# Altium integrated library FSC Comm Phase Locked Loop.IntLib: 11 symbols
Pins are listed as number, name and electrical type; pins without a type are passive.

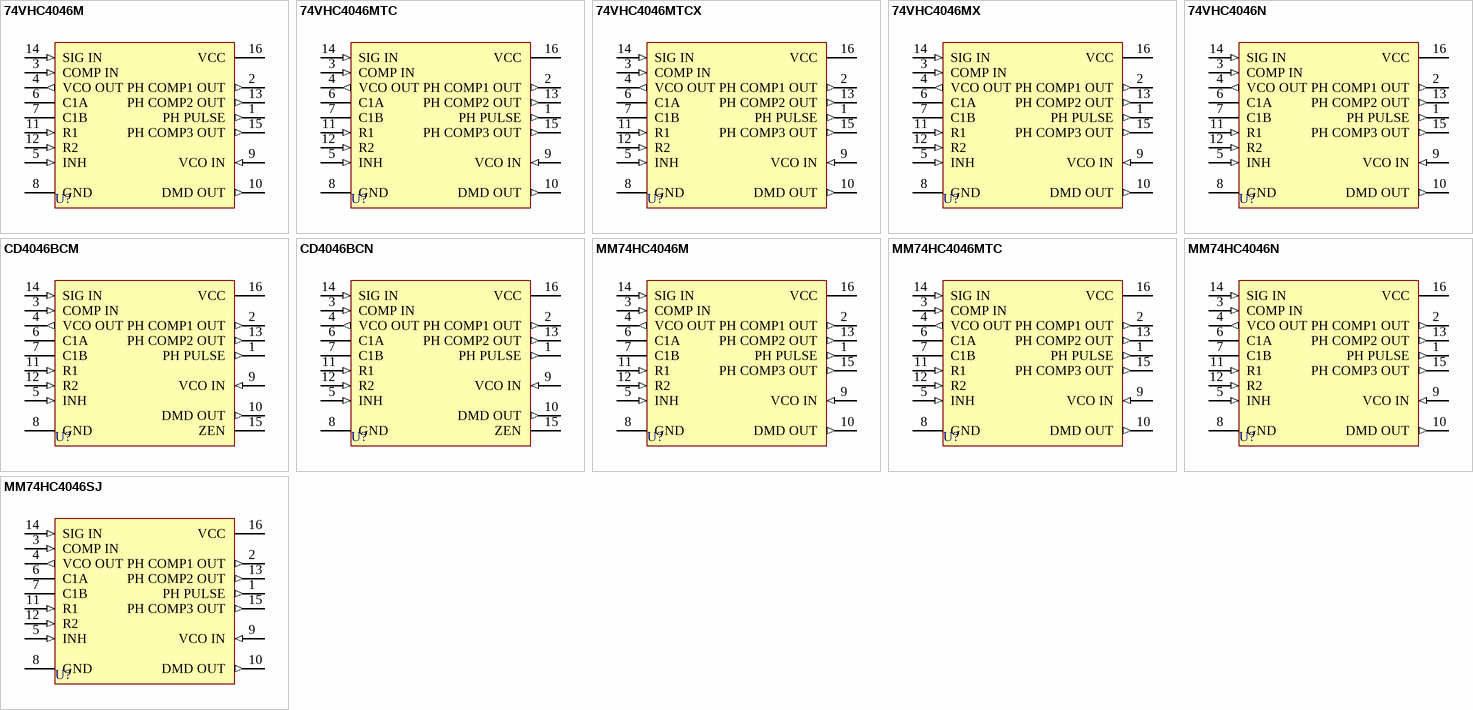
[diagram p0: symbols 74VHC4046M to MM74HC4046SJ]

## 74VHC4046M
designator U?
CMOS Phase Lock Loop
footprint M16A_N (SOIC, 16-Leads, Body 9.9x3.9mm, Pitch 1.27mm, IPC Medium Density)
footprint M16A_L (SOIC, 16-Leads, Body 9.9x3.9mm, Pitch 1.27mm, IPC High Density)
footprint M16A_M (SOIC, 16-Leads, Body 9.9x3.9mm, Pitch 1.27mm, IPC Low Density)
3D model M16A (16-Pin Small Outline Integrated Circuit 1.27 mm Pitch)
pins: 1 PH PULSE (out), 2 PH COMP1 OUT (out), 3 COMP IN (in), 4 VCO OUT (out), 5 INH (in), 6 C1A, 7 C1B, 8 GND (power), 9 VCO IN (in), 10 DMD OUT (out), 11 R1 (in), 12 R2 (in), 13 PH COMP2 OUT (out), 14 SIG IN (in), 15 PH COMP3 OUT (out), 16 VCC (power)

## 74VHC4046MTC
designator U?
CMOS Phase Lock Loop
footprint MTC16 (Shrink Small Outline; 16 Leads; Body Width 4.4 mm; Pitch 0.65 mm)
3D model MTC16 (Shrink Small Outline; 16 Leads; Body Width 4.4 mm; Pitch 0.65 mm)
pins: 1 PH PULSE (out), 2 PH COMP1 OUT (out), 3 COMP IN (in), 4 VCO OUT (out), 5 INH (in), 6 C1A, 7 C1B, 8 GND (power), 9 VCO IN (in), 10 DMD OUT (out), 11 R1 (in), 12 R2 (in), 13 PH COMP2 OUT (out), 14 SIG IN (in), 15 PH COMP3 OUT (out), 16 VCC (power)

## 74VHC4046MTCX
designator U?
CMOS Phase Lock Loop
footprint MTC16 (Shrink Small Outline; 16 Leads; Body Width 4.4 mm; Pitch 0.65 mm)
3D model MTC16 (Shrink Small Outline; 16 Leads; Body Width 4.4 mm; Pitch 0.65 mm)
pins: 1 PH PULSE (out), 2 PH COMP1 OUT (out), 3 COMP IN (in), 4 VCO OUT (out), 5 INH (in), 6 C1A, 7 C1B, 8 GND (power), 9 VCO IN (in), 10 DMD OUT (out), 11 R1 (in), 12 R2 (in), 13 PH COMP2 OUT (out), 14 SIG IN (in), 15 PH COMP3 OUT (out), 16 VCC (power)

## 74VHC4046MX
designator U?
CMOS Phase Lock Loop
footprint M16A_N (SOIC, 16-Leads, Body 9.9x3.9mm, Pitch 1.27mm, IPC Medium Density)
footprint M16A_L (SOIC, 16-Leads, Body 9.9x3.9mm, Pitch 1.27mm, IPC High Density)
footprint M16A_M (SOIC, 16-Leads, Body 9.9x3.9mm, Pitch 1.27mm, IPC Low Density)
3D model M16A (16-Pin Small Outline Integrated Circuit 1.27 mm Pitch)
pins: 1 PH PULSE (out), 2 PH COMP1 OUT (out), 3 COMP IN (in), 4 VCO OUT (out), 5 INH (in), 6 C1A, 7 C1B, 8 GND (power), 9 VCO IN (in), 10 DMD OUT (out), 11 R1 (in), 12 R2 (in), 13 PH COMP2 OUT (out), 14 SIG IN (in), 15 PH COMP3 OUT (out), 16 VCC (power)

## 74VHC4046N
designator U?
CMOS Phase Lock Loop
footprint N16E (DIP; 16 Leads; Row Spacing 7.62 mm; Pitch 2.54 mm)
3D model N16E (DIP; 16 Leads; Row Spacing 7.62 mm; Pitch 2.54 mm)
pins: 1 PH PULSE (out), 2 PH COMP1 OUT (out), 3 COMP IN (in), 4 VCO OUT (out), 5 INH (in), 6 C1A, 7 C1B, 8 GND (power), 9 VCO IN (in), 10 DMD OUT (out), 11 R1 (in), 12 R2 (in), 13 PH COMP2 OUT (out), 14 SIG IN (in), 15 PH COMP3 OUT (out), 16 VCC (power)

## CD4046BCM
designator U?
Micropower Phase-Locked Loop
footprint M16A_N (SOIC, 16-Leads, Body 9.9x3.9mm, Pitch 1.27mm, IPC Medium Density)
footprint M16A_L (SOIC, 16-Leads, Body 9.9x3.9mm, Pitch 1.27mm, IPC High Density)
footprint M16A_M (SOIC, 16-Leads, Body 9.9x3.9mm, Pitch 1.27mm, IPC Low Density)
3D model M16A (16-Pin Small Outline Integrated Circuit 1.27 mm Pitch)
pins: 1 PH PULSE (out), 2 PH COMP1 OUT (out), 3 COMP IN (in), 4 VCO OUT (out), 5 INH (in), 6 C1A, 7 C1B, 8 GND (power), 9 VCO IN (in), 10 DMD OUT (out), 11 R1 (in), 12 R2 (in), 13 PH COMP2 OUT (out), 14 SIG IN (in), 15 ZEN, 16 VCC (power)

## CD4046BCN
designator U?
Micropower Phase-Locked Loop
footprint N16E (DIP; 16 Leads; Row Spacing 7.62 mm; Pitch 2.54 mm)
3D model N16E (DIP; 16 Leads; Row Spacing 7.62 mm; Pitch 2.54 mm)
pins: 1 PH PULSE (out), 2 PH COMP1 OUT (out), 3 COMP IN (in), 4 VCO OUT (out), 5 INH (in), 6 C1A, 7 C1B, 8 GND (power), 9 VCO IN (in), 10 DMD OUT (out), 11 R1 (in), 12 R2 (in), 13 PH COMP2 OUT (out), 14 SIG IN (in), 15 ZEN, 16 VCC (power)

## MM74HC4046M
designator U?
CMOS Phase-Locked Loop
footprint M16A_N (SOIC, 16-Leads, Body 9.9x3.9mm, Pitch 1.27mm, IPC Medium Density)
footprint M16A_L (SOIC, 16-Leads, Body 9.9x3.9mm, Pitch 1.27mm, IPC High Density)
footprint M16A_M (SOIC, 16-Leads, Body 9.9x3.9mm, Pitch 1.27mm, IPC Low Density)
3D model M16A (16-Pin Small Outline Integrated Circuit 1.27 mm Pitch)
signal-integrity model MM74HC4046M
pins: 1 PH PULSE (out), 2 PH COMP1 OUT (out), 3 COMP IN (in), 4 VCO OUT (out), 5 INH (in), 6 C1A, 7 C1B, 8 GND (power), 9 VCO IN (in), 10 DMD OUT (out), 11 R1 (in), 12 R2 (in), 13 PH COMP2 OUT (out), 14 SIG IN (in), 15 PH COMP3 OUT (out), 16 VCC (power)

## MM74HC4046MTC
designator U?
CMOS Phase-Locked Loop
footprint MTC16 (Shrink Small Outline; 16 Leads; Body Width 4.4 mm; Pitch 0.65 mm)
3D model MTC16 (Shrink Small Outline; 16 Leads; Body Width 4.4 mm; Pitch 0.65 mm)
signal-integrity model MM74HC4046MTC
pins: 1 PH PULSE (out), 2 PH COMP1 OUT (out), 3 COMP IN (in), 4 VCO OUT (out), 5 INH (in), 6 C1A, 7 C1B, 8 GND (power), 9 VCO IN (in), 10 DMD OUT (out), 11 R1 (in), 12 R2 (in), 13 PH COMP2 OUT (out), 14 SIG IN (in), 15 PH COMP3 OUT (out), 16 VCC (power)

## MM74HC4046N
designator U?
CMOS Phase-Locked Loop
footprint N16E (DIP; 16 Leads; Row Spacing 7.62 mm; Pitch 2.54 mm)
3D model N16E (DIP; 16 Leads; Row Spacing 7.62 mm; Pitch 2.54 mm)
signal-integrity model MM74HC4046N
pins: 1 PH PULSE (out), 2 PH COMP1 OUT (out), 3 COMP IN (in), 4 VCO OUT (out), 5 INH (in), 6 C1A, 7 C1B, 8 GND (power), 9 VCO IN (in), 10 DMD OUT (out), 11 R1 (in), 12 R2 (in), 13 PH COMP2 OUT (out), 14 SIG IN (in), 15 PH COMP3 OUT (out), 16 VCC (power)

## MM74HC4046SJ
designator U?
CMOS Phase-Locked Loop
footprint M16D_N (SOP, 16-Leads, Body 10.1x5.3mm, Pitch 1.27mm, IPC Medium Density)
footprint M16D_L (SOP, 16-Leads, Body 10.1x5.3mm, Pitch 1.27mm, IPC High Density)
footprint M16D_M (SOP, 16-Leads, Body 10.1x5.3mm, Pitch 1.27mm, IPC Low Density)
3D model M16D (16-Pin Small Outline Package 1.27 mm Pitch)
signal-integrity model MM74HC4046SJ
pins: 1 PH PULSE (out), 2 PH COMP1 OUT (out), 3 COMP IN (in), 4 VCO OUT (out), 5 INH (in), 6 C1A, 7 C1B, 8 GND (power), 9 VCO IN (in), 10 DMD OUT (out), 11 R1 (in), 12 R2 (in), 13 PH COMP2 OUT (out), 14 SIG IN (in), 15 PH COMP3 OUT (out), 16 VCC (power)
